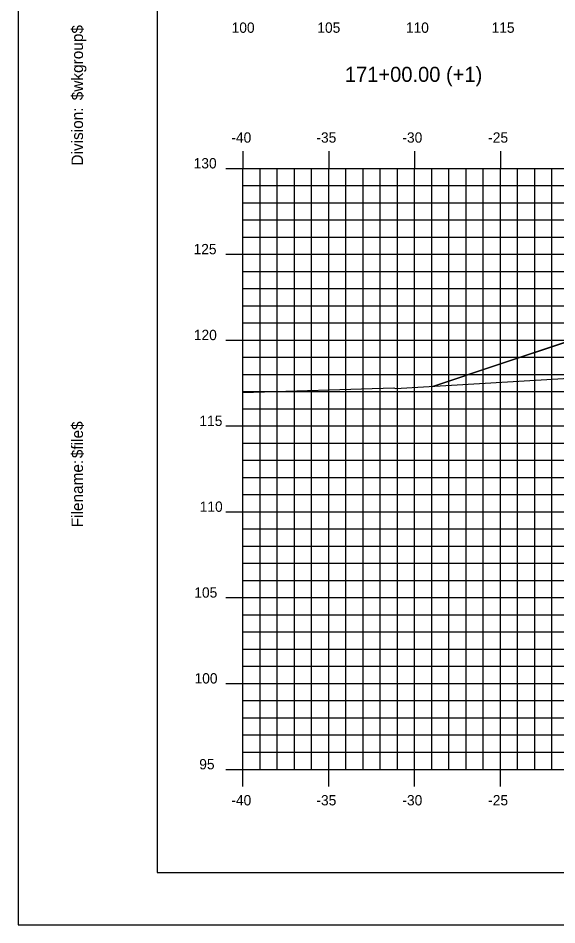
# Model space of a CAD drawing. Extents: x 850598 to 870284, y 366541 to 366651.
# Drawn here: x 855920 to 855951.3, y 366541.2 to 366594 of the extents above; entities that cross this region are included whole.
import ezdxf

# ---------------------------------------------------------------- set-up
doc = ezdxf.new("R2010")
doc.units = 0
for name, color, linetype in [('BORDER', 7, 'Continuous'), ('D_Roadway_Centerline', 7, 'Continuous'), ('D_Roadway_SlopeLines', 7, 'Continuous'), ('H_V ANNOTATION', 7, 'Continuous'), ('MAJOR', 7, 'Continuous'), ('MINOR', 7, 'Continuous'), ('PLOT BOUNDARY', 7, 'Continuous'), ('S_Roadway_Centerline', 7, 'Continuous')]:
    doc.layers.add(name, color=color, linetype=linetype)

msp = doc.modelspace()

# ---------------------------------------------------------------- linework, layer by layer
at = {"layer": 'BORDER'}
for p, q in [((855928.054, 366649.225), (855928.054, 366544.225)), ((855928.054, 366544.225), (856088.054, 366544.225))]:
    msp.add_line(p, q, dxfattribs=at)
at = {"layer": 'D_Roadway_Centerline'}
msp.add_lwpolyline([(855944.118, 366572.532), (855948.054, 366573.844), (855951.856, 366575.111), (855958.054, 366577.177), (855962.054, 366577.417), (855973.054, 366577.747), (855984.054, 366577.417), (855988.054, 366577.177), (855990.054, 366577.057), (855996.054, 366575.057), (856046.318, 366563.225), (856061.944, 366559.547), (856071.806, 366557.225), (856073.054, 366557.225)], dxfattribs=at)
at = {"layer": 'D_Roadway_SlopeLines'}
for points in [[(855962.054, 366577.417), (855958.054, 366577.177), (855948.054, 366573.844)], [(855948.054, 366573.844), (855944.118, 366572.532)]]:
    msp.add_lwpolyline(points, dxfattribs=at)
at = {"layer": 'MAJOR'}
for p, q in [((855933.054, 366586.227), (855933.054, 366585.225)), ((855933.054, 366586.227), (855933.054, 366585.225)), ((855938.054, 366586.227), (855938.054, 366585.225)), ((855938.054, 366586.227), (855938.054, 366585.225)), ((855943.054, 366586.227), (855943.054, 366585.225)), ((855943.054, 366586.227), (855943.054, 366585.225)), ((855948.054, 366586.227), (855948.054, 366585.225)), ((855948.054, 366586.227), (855948.054, 366585.225)), ((855932.052, 366585.225), (855933.054, 366585.225)), ((855932.052, 366585.225), (855933.054, 366585.225)), ((855933.054, 366585.225), (856073.054, 366585.225)), ((855933.054, 366550.225), (855933.054, 366585.225)), ((855933.054, 366550.225), (855933.054, 366585.225)), ((855933.054, 366585.225), (856073.054, 366585.225)), ((855933.054, 366585.225), (856073.054, 366585.225)), ((855933.054, 366550.225), (855933.054, 366585.225)), ((855933.054, 366550.225), (855933.054, 366585.225)), ((855933.054, 366585.225), (856073.054, 366585.225)), ((855938.054, 366550.225), (855938.054, 366585.225)), ((855938.054, 366550.225), (855938.054, 366585.225)), ((855943.054, 366550.225), (855943.054, 366585.225)), ((855943.054, 366550.225), (855943.054, 366585.225)), ((855948.054, 366550.225), (855948.054, 366585.225)), ((855948.054, 366550.225), (855948.054, 366585.225)), ((855932.052, 366580.225), (855933.054, 366580.225)), ((855932.052, 366580.225), (855933.054, 366580.225)), ((855933.054, 366580.225), (856073.054, 366580.225)), ((855933.054, 366580.225), (856073.054, 366580.225)), ((855932.052, 366575.225), (855933.054, 366575.225)), ((855932.052, 366575.225), (855933.054, 366575.225)), ((855933.054, 366575.225), (856073.054, 366575.225)), ((855933.054, 366575.225), (856073.054, 366575.225)), ((855932.052, 366570.225), (855933.054, 366570.225)), ((855932.052, 366570.225), (855933.054, 366570.225)), ((855933.054, 366570.225), (856073.054, 366570.225)), ((855933.054, 366570.225), (856073.054, 366570.225)), ((855932.052, 366565.225), (855933.054, 366565.225)), ((855932.052, 366565.225), (855933.054, 366565.225)), ((855933.054, 366565.225), (856073.054, 366565.225)), ((855933.054, 366565.225), (856073.054, 366565.225)), ((855932.052, 366560.225), (855933.054, 366560.225)), ((855932.052, 366560.225), (855933.054, 366560.225)), ((855933.054, 366560.225), (856073.054, 366560.225)), ((855933.054, 366560.225), (856073.054, 366560.225)), ((855932.052, 366555.225), (855933.054, 366555.225)), ((855932.052, 366555.225), (855933.054, 366555.225)), ((855933.054, 366555.225), (856073.054, 366555.225)), ((855933.054, 366555.225), (856073.054, 366555.225)), ((855932.052, 366550.225), (855933.054, 366550.225)), ((855932.052, 366550.225), (855933.054, 366550.225)), ((855933.054, 366550.225), (856073.054, 366550.225)), ((855933.054, 366550.225), (856073.054, 366550.225)), ((855933.054, 366549.223), (855933.054, 366550.225)), ((855933.054, 366550.225), (856073.054, 366550.225)), ((855933.054, 366550.225), (856073.054, 366550.225)), ((855933.054, 366549.223), (855933.054, 366550.225)), ((855938.054, 366549.223), (855938.054, 366550.225)), ((855938.054, 366549.223), (855938.054, 366550.225)), ((855943.054, 366549.223), (855943.054, 366550.225)), ((855943.054, 366549.223), (855943.054, 366550.225)), ((855948.054, 366549.223), (855948.054, 366550.225)), ((855948.054, 366549.223), (855948.054, 366550.225))]:
    msp.add_line(p, q, dxfattribs=at)
at = {"layer": 'MINOR'}
for p, q in [((855934.054, 366550.225), (855934.054, 366585.225)), ((855934.054, 366550.225), (855934.054, 366585.225)), ((855935.054, 366550.225), (855935.054, 366585.225)), ((855935.054, 366550.225), (855935.054, 366585.225)), ((855936.054, 366550.225), (855936.054, 366585.225)), ((855936.054, 366550.225), (855936.054, 366585.225)), ((855937.054, 366550.225), (855937.054, 366585.225)), ((855937.054, 366550.225), (855937.054, 366585.225)), ((855939.054, 366550.225), (855939.054, 366585.225)), ((855939.054, 366550.225), (855939.054, 366585.225)), ((855940.054, 366550.225), (855940.054, 366585.225)), ((855940.054, 366550.225), (855940.054, 366585.225)), ((855941.054, 366550.225), (855941.054, 366585.225)), ((855941.054, 366550.225), (855941.054, 366585.225)), ((855942.054, 366550.225), (855942.054, 366585.225)), ((855942.054, 366550.225), (855942.054, 366585.225)), ((855944.054, 366550.225), (855944.054, 366585.225)), ((855944.054, 366550.225), (855944.054, 366585.225)), ((855945.054, 366550.225), (855945.054, 366585.225)), ((855945.054, 366550.225), (855945.054, 366585.225)), ((855946.054, 366550.225), (855946.054, 366585.225)), ((855946.054, 366550.225), (855946.054, 366585.225)), ((855947.054, 366550.225), (855947.054, 366585.225)), ((855947.054, 366550.225), (855947.054, 366585.225)), ((855949.054, 366550.225), (855949.054, 366585.225)), ((855949.054, 366550.225), (855949.054, 366585.225)), ((855950.054, 366550.225), (855950.054, 366585.225)), ((855950.054, 366550.225), (855950.054, 366585.225)), ((855951.054, 366550.225), (855951.054, 366585.225)), ((855951.054, 366550.225), (855951.054, 366585.225)), ((855933.054, 366584.225), (856073.054, 366584.225)), ((855933.054, 366584.225), (855934.056, 366584.225)), ((855933.054, 366584.225), (856073.054, 366584.225)), ((855933.054, 366584.225), (855934.056, 366584.225)), ((855933.054, 366583.225), (856073.054, 366583.225)), ((855933.054, 366583.225), (855934.056, 366583.225)), ((855933.054, 366583.225), (856073.054, 366583.225)), ((855933.054, 366583.225), (855934.056, 366583.225)), ((855933.054, 366582.225), (856073.054, 366582.225)), ((855933.054, 366582.225), (855934.056, 366582.225)), ((855933.054, 366582.225), (856073.054, 366582.225)), ((855933.054, 366582.225), (855934.056, 366582.225)), ((855933.054, 366581.225), (856073.054, 366581.225)), ((855933.054, 366581.225), (855934.056, 366581.225)), ((855933.054, 366581.225), (856073.054, 366581.225)), ((855933.054, 366581.225), (855934.056, 366581.225)), ((855933.054, 366579.225), (856073.054, 366579.225)), ((855933.054, 366579.225), (855934.056, 366579.225)), ((855933.054, 366579.225), (856073.054, 366579.225)), ((855933.054, 366579.225), (855934.056, 366579.225)), ((855933.054, 366578.225), (856073.054, 366578.225)), ((855933.054, 366578.225), (855934.056, 366578.225)), ((855933.054, 366578.225), (856073.054, 366578.225)), ((855933.054, 366578.225), (855934.056, 366578.225)), ((855933.054, 366577.225), (856073.054, 366577.225)), ((855933.054, 366577.225), (855934.056, 366577.225)), ((855933.054, 366577.225), (856073.054, 366577.225)), ((855933.054, 366577.225), (855934.056, 366577.225)), ((855933.054, 366576.225), (856073.054, 366576.225)), ((855933.054, 366576.225), (855934.056, 366576.225)), ((855933.054, 366576.225), (856073.054, 366576.225)), ((855933.054, 366576.225), (855934.056, 366576.225)), ((855933.054, 366574.225), (856073.054, 366574.225)), ((855933.054, 366574.225), (855934.056, 366574.225)), ((855933.054, 366574.225), (856073.054, 366574.225)), ((855933.054, 366574.225), (855934.056, 366574.225)), ((855933.054, 366573.225), (856073.054, 366573.225)), ((855933.054, 366573.225), (855934.056, 366573.225)), ((855933.054, 366573.225), (856073.054, 366573.225)), ((855933.054, 366573.225), (855934.056, 366573.225)), ((855933.054, 366572.225), (856073.054, 366572.225)), ((855933.054, 366572.225), (855934.056, 366572.225)), ((855933.054, 366572.225), (856073.054, 366572.225)), ((855933.054, 366572.225), (855934.056, 366572.225)), ((855933.054, 366571.225), (856073.054, 366571.225)), ((855933.054, 366571.225), (855934.056, 366571.225)), ((855933.054, 366571.225), (856073.054, 366571.225)), ((855933.054, 366571.225), (855934.056, 366571.225)), ((855933.054, 366569.225), (856073.054, 366569.225)), ((855933.054, 366569.225), (855934.056, 366569.225)), ((855933.054, 366569.225), (856073.054, 366569.225)), ((855933.054, 366569.225), (855934.056, 366569.225)), ((855933.054, 366568.225), (856073.054, 366568.225)), ((855933.054, 366568.225), (855934.056, 366568.225)), ((855933.054, 366568.225), (856073.054, 366568.225)), ((855933.054, 366568.225), (855934.056, 366568.225)), ((855933.054, 366567.225), (856073.054, 366567.225)), ((855933.054, 366567.225), (855934.056, 366567.225)), ((855933.054, 366567.225), (856073.054, 366567.225)), ((855933.054, 366567.225), (855934.056, 366567.225)), ((855933.054, 366566.225), (856073.054, 366566.225)), ((855933.054, 366566.225), (855934.056, 366566.225)), ((855933.054, 366566.225), (856073.054, 366566.225)), ((855933.054, 366566.225), (855934.056, 366566.225)), ((855933.054, 366564.225), (856073.054, 366564.225)), ((855933.054, 366564.225), (855934.056, 366564.225)), ((855933.054, 366564.225), (856073.054, 366564.225)), ((855933.054, 366564.225), (855934.056, 366564.225)), ((855933.054, 366563.225), (856073.054, 366563.225)), ((855933.054, 366563.225), (855934.056, 366563.225)), ((855933.054, 366563.225), (856073.054, 366563.225)), ((855933.054, 366563.225), (855934.056, 366563.225)), ((855933.054, 366562.225), (856073.054, 366562.225)), ((855933.054, 366562.225), (855934.056, 366562.225)), ((855933.054, 366562.225), (856073.054, 366562.225)), ((855933.054, 366562.225), (855934.056, 366562.225)), ((855933.054, 366561.225), (856073.054, 366561.225)), ((855933.054, 366561.225), (855934.056, 366561.225)), ((855933.054, 366561.225), (856073.054, 366561.225)), ((855933.054, 366561.225), (855934.056, 366561.225)), ((855933.054, 366559.225), (856073.054, 366559.225)), ((855933.054, 366559.225), (855934.056, 366559.225)), ((855933.054, 366559.225), (856073.054, 366559.225)), ((855933.054, 366559.225), (855934.056, 366559.225)), ((855933.054, 366558.225), (856073.054, 366558.225)), ((855933.054, 366558.225), (855934.056, 366558.225)), ((855933.054, 366558.225), (856073.054, 366558.225)), ((855933.054, 366558.225), (855934.056, 366558.225)), ((855933.054, 366557.225), (856073.054, 366557.225)), ((855933.054, 366557.225), (855934.056, 366557.225)), ((855933.054, 366557.225), (856073.054, 366557.225)), ((855933.054, 366557.225), (855934.056, 366557.225)), ((855933.054, 366556.225), (856073.054, 366556.225)), ((855933.054, 366556.225), (855934.056, 366556.225)), ((855933.054, 366556.225), (856073.054, 366556.225)), ((855933.054, 366556.225), (855934.056, 366556.225)), ((855933.054, 366554.225), (856073.054, 366554.225)), ((855933.054, 366554.225), (855934.056, 366554.225)), ((855933.054, 366554.225), (856073.054, 366554.225)), ((855933.054, 366554.225), (855934.056, 366554.225)), ((855933.054, 366553.225), (856073.054, 366553.225)), ((855933.054, 366553.225), (855934.056, 366553.225)), ((855933.054, 366553.225), (856073.054, 366553.225)), ((855933.054, 366553.225), (855934.056, 366553.225)), ((855933.054, 366552.225), (856073.054, 366552.225)), ((855933.054, 366552.225), (855934.056, 366552.225)), ((855933.054, 366552.225), (856073.054, 366552.225)), ((855933.054, 366552.225), (855934.056, 366552.225)), ((855933.054, 366551.225), (856073.054, 366551.225)), ((855933.054, 366551.225), (855934.056, 366551.225)), ((855933.054, 366551.225), (856073.054, 366551.225)), ((855933.054, 366551.225), (855934.056, 366551.225))]:
    msp.add_line(p, q, dxfattribs=at)
at = {"layer": 'PLOT BOUNDARY'}
msp.add_lwpolyline([(855919.961, 366541.166), (856089.961, 366541.166), (856089.961, 366651.166), (855919.961, 366651.166)], close=True, dxfattribs=at)
at = {"layer": 'S_Roadway_Centerline'}
msp.add_lwpolyline([(855933.054, 366572.18), (855941.836, 366572.446), (855941.937, 366572.401), (855958.25, 366573.382), (855980.032, 366574.63), (855981.616, 366574.892), (855981.916, 366574.866), (855985.454, 366573.722), (855993.641, 366575.472), (855994.485, 366575.642), (855994.637, 366575.675), (855998.159, 366576.203), (856010.354, 366576.816), (856013.332, 366576.936), (856016.317, 366576.805), (856028.199, 366576.305), (856028.96, 366576.202), (856032.024, 366575.804), (856037.834, 366576.922), (856040.034, 366577.226), (856054.317, 366569.904), (856066.71, 366560.873), (856073.054, 366558.329)], dxfattribs=at)

# ---------------------------------------------------------------- texts
at = {"layer": 'BORDER'}
for s, p in [('$wkgroup$', (855923.739, 366589.195)), ('Division:', (855923.739, 366585.391)), ('$file$', (855923.739, 366568.351)), ('Filename:', (855923.739, 366564.324))]:
    msp.add_text(s, height=0.6696, rotation=90, dxfattribs=at).set_placement(p)
at = {"layer": 'H_V ANNOTATION'}
for s, height, p in [('100', 0.6, (855932.396, 366593.125)), ('105', 0.6, (855937.388, 366593.125)), ('110', 0.6, (855942.546, 366593.125)), ('115', 0.6, (855947.538, 366593.125)), ('171+00.00 (+1)', 0.87498, (855938.993, 366590.268)), ('-40', 0.6, (855932.38, 366586.725)), ('-35', 0.6, (855937.334, 366586.725)), ('-30', 0.6, (855942.342, 366586.725)), ('-25', 0.6, (855947.339, 366586.725)), ('130', 0.6, (855930.184, 366585.225)), ('125', 0.6, (855930.179, 366580.225)), ('120', 0.6, (855930.195, 366575.225)), ('115', 0.6, (855930.521, 366570.225)), ('110', 0.6, (855930.537, 366565.225)), ('105', 0.6, (855930.221, 366560.225)), ('100', 0.6, (855930.237, 366555.225)), ('95', 0.6, (855930.51, 366550.225)), ('-40', 0.6, (855932.38, 366548.125)), ('-35', 0.6, (855937.334, 366548.125)), ('-30', 0.6, (855942.342, 366548.125)), ('-25', 0.6, (855947.339, 366548.125))]:
    msp.add_text(s, height=height, dxfattribs=at).set_placement(p)

doc.saveas('drawing.dxf')
